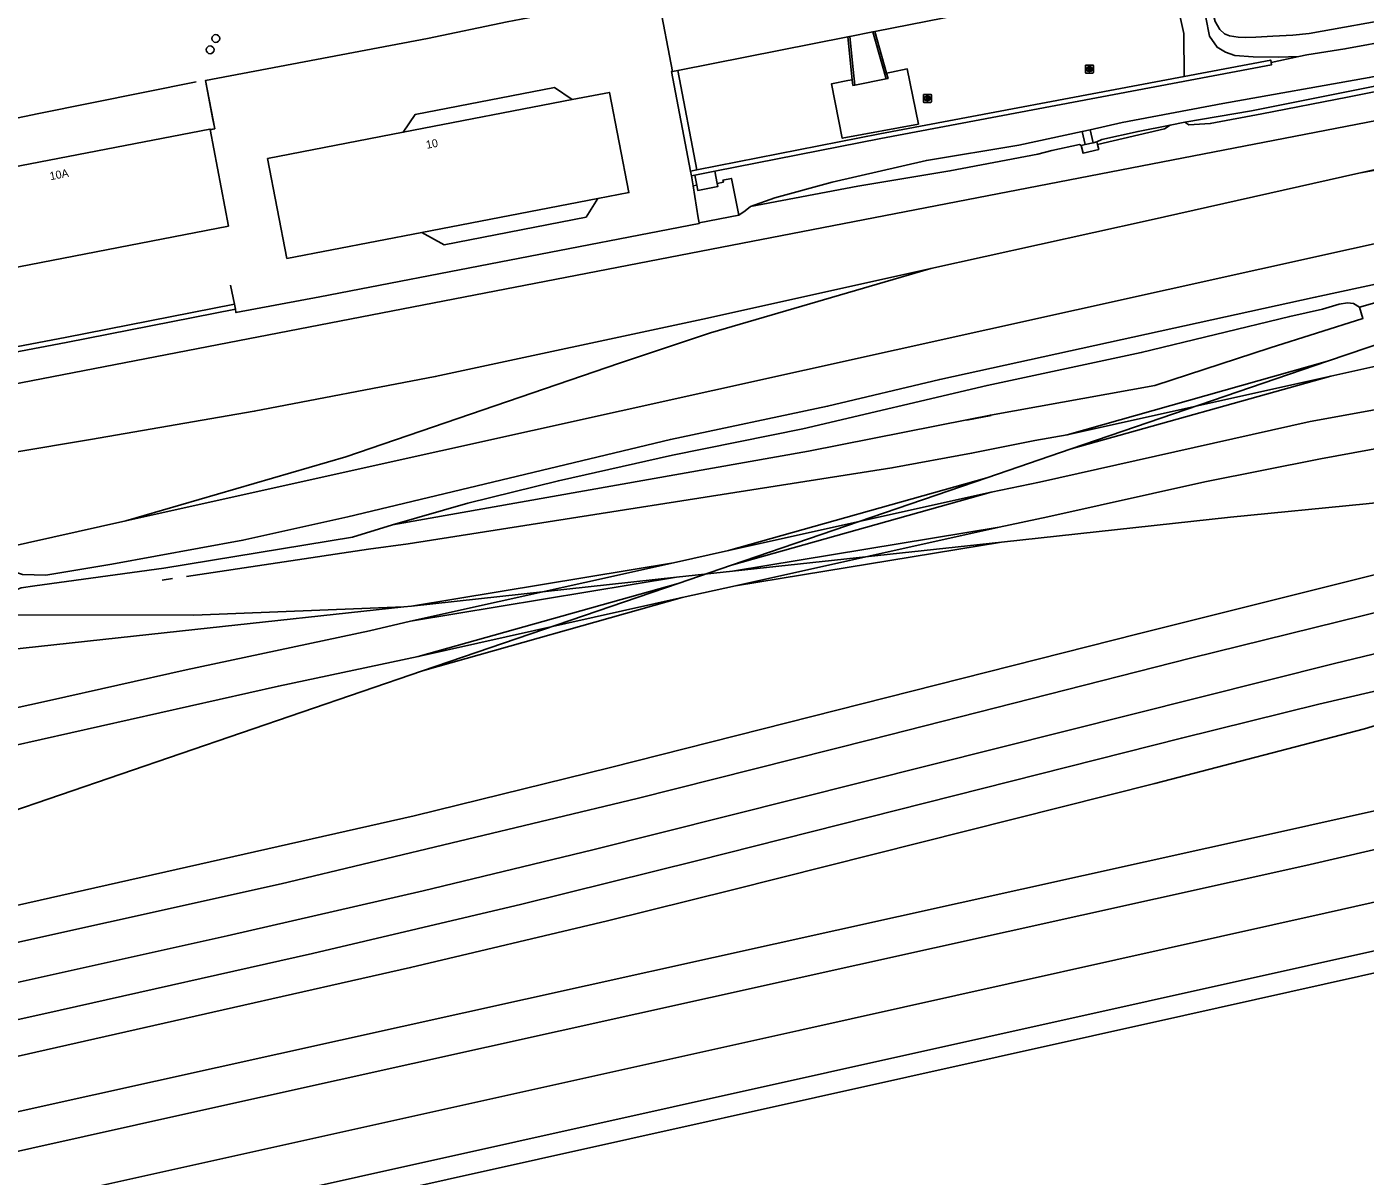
# Model space of a CAD drawing. Extents: x 161477 to 163040, y 383680 to 384868.
# Drawn here: x 161855.5 to 162022.7, y 383800 to 383943.7 of the extents above; entities that cross this region are included whole.
import ezdxf

# ---------------------------------------------------------------- set-up
doc = ezdxf.new("R2010")
doc.units = 0
for name, color, linetype in [('IMGEO_Boom', 7, 'Continuous'), ('IMGEO_Erf', 7, 'Continuous'), ('IMGEO_Grasland_overig', 7, 'Continuous'), ('IMGEO_Groenvoorziening', 7, 'Continuous'), ('IMGEO_Hek', 7, 'Continuous'), ('IMGEO_Loofbos', 7, 'Continuous'), ('IMGEO_Muur', 7, 'Continuous'), ('IMGEO_Pand', 7, 'Continuous'), ('IMGEO_Pand_nummerreeks', 7, 'Continuous'), ('IMGEO_Pand_overbouw', 7, 'Continuous'), ('IMGEO_Parkeervlak_halfverhard', 7, 'Continuous'), ('IMGEO_Rijbaan_lokaal_gesloten', 7, 'Continuous'), ('IMGEO_Rioolput', 7, 'Continuous'), ('IMGEO_Spoor', 7, 'Continuous'), ('IMGEO_Spoorbaan_halfverhard', 7, 'Continuous'), ('IMGEO_Terreindeel_halfverhard', 7, 'Continuous'), ('IMGEO_Terreindeel_onvherhard', 7, 'Continuous'), ('IMGEO_Terreindeel_open', 7, 'Continuous'), ('IMGEO_Voetpad_op_trap', 7, 'Continuous'), ('IMGEO_Waterloop', 7, 'Continuous')]:
    doc.layers.add(name, color=color, linetype=linetype)

msp = doc.modelspace()

# ---------------------------------------------------------------- linework, layer by layer
at = {"layer": 'IMGEO_Boom'}
for centre in [(161879.07, 383942.21), (161878.36, 383940.8)]:
    msp.add_circle(centre, 0.489, dxfattribs=at)
at = {"layer": 'IMGEO_Erf'}
msp.add_lwpolyline([(161936.1, 383938.1), (161934.4, 383947), (161925.12, 383945.87), (161925.09, 383946.14)], dxfattribs=at)
at = {"layer": 'IMGEO_Grasland_overig'}
for points in [[(162042.14, 383941.17), (162039.02, 383940.6), (162023.15, 383937.33), (162004.87, 383934.08), (161992.3, 383931.73), (161988.29, 383930.8)], [(162000.1, 383931.74), (162008.45, 383933.19), (162033.01, 383938.09)], [(161987.31, 383930.57), (161979.37, 383928.9), (161967.83, 383926.98), (161956.08, 383924.25), (161948.92, 383922.3), (161945.86, 383921.22)], [(161998.3, 383931.38), (161994.28, 383930.59), (161989.77, 383929.58), (161989.13, 383929.3)], [(161987.69, 383928.96), (161987.18, 383928.85)], [(161989.13, 383929.3), (161988.66, 383929.19)], [(161989.21, 383928.98), (161989.13, 383929.3)]]:
    msp.add_lwpolyline(points, dxfattribs=at)
at = {"layer": 'IMGEO_Groenvoorziening'}
msp.add_lwpolyline([(161925.09, 383946.14), (161915.47, 383944.28), (161905.53, 383942.23), (161877.77, 383936.95), (161878.93, 383930.93), (161878.36, 383930.82)], dxfattribs=at)
at = {"layer": 'IMGEO_Hek'}
for points in [[(161856.98, 383932.82), (161876.6, 383936.81)], [(161877.77, 383936.95), (161878.66, 383932.31)], [(161839.61, 383929.21), (161856.98, 383932.82)], [(161878.66, 383932.31), (161878.93, 383930.93)], [(161878.93, 383930.93), (161878.31, 383930.81)], [(161880.92, 383911.38), (161881.39, 383909.02), (161881.52, 383908.4), (161881.58, 383907.97), (161892.06, 383909.93), (161939.47, 383919.11), (161939.46, 383919.16), (161939.34, 383919.81), (161938.69, 383923.78), (161938.48, 383925.04), (161938.37, 383925.63)], [(161824.04, 383897.35), (161831.56, 383898.7), (161834.04, 383899.21), (161860.38, 383904.24), (161881.52, 383908.4)], [(161975.92, 383895.12), (161972.88, 383894.51)]]:
    msp.add_lwpolyline(points, dxfattribs=at)
at = {"layer": 'IMGEO_Loofbos'}
for points in [[(162014.37, 383939.95), (162011.76, 383939.87), (162008.65, 383939.9), (162006.37, 383940.1), (162005.22, 383940.5), (162004.15, 383941.12), (162003.21, 383942.49), (162002.73, 383944.84), (162001.35, 383953.25), (161994.44, 384009.28)], [(162010.9, 383939.21), (162014.37, 383939.95)]]:
    msp.add_lwpolyline(points, dxfattribs=at)
at = {"layer": 'IMGEO_Muur'}
for points in [[(161915.47, 383944.28), (161905.53, 383942.23)], [(161877.77, 383936.95), (161905.53, 383942.23)], [(161958.02, 383942.41), (161958.26, 383942.46)], [(161958.58, 383937.05), (161958.02, 383942.41)], [(161958.26, 383942.46), (161958.69, 383938.35), (161958.9, 383936.36)], [(161961.14, 383943.03), (161961.38, 383943.08)], [(161962.8, 383937.16), (161962.26, 383939.08), (161961.14, 383943.03)], [(161961.38, 383943.08), (161962.86, 383937.89)], [(161941.42, 383925.62), (161962.13, 383929.7), (162010.96, 383938.92), (162010.9, 383939.21)], [(162010.9, 383939.21), (162010.85, 383939.51), (162000.03, 383937.46)], [(161936.1, 383938.1), (161935.99, 383938.07), (161938.37, 383925.63)], [(161936.79, 383938.23), (161936.1, 383938.1)], [(161939.17, 383925.79), (161936.79, 383938.23)], [(161939.17, 383925.79), (161962.02, 383930.29), (162000.03, 383937.46)], [(161962.86, 383937.89), (161963.05, 383937.22), (161962.8, 383937.16)], [(161958.9, 383936.36), (161958.65, 383936.34), (161958.58, 383937.05)], [(161938.37, 383925.63), (161939.17, 383925.79)], [(161938.37, 383925.63), (161938.48, 383925.04)], [(161941.42, 383925.62), (161938.9, 383925.12)], [(161938.9, 383925.12), (161938.48, 383925.04)]]:
    msp.add_lwpolyline(points, dxfattribs=at)
at = {"layer": 'IMGEO_Pand'}
for points in [[(161885.53, 383927.22), (161902.48, 383930.5), (161923.58, 383934.58), (161928.25, 383935.48), (161930.67, 383922.96), (161926.81, 383922.22), (161904.82, 383917.98), (161887.95, 383914.72), (161885.53, 383927.22)], [(161878.36, 383930.82), (161880.65, 383918.77), (161847.56, 383912.36), (161842.65, 383911.41), (161840.34, 383923.54), (161840.51, 383923.57)], [(161840.51, 383923.57), (161845.25, 383924.49), (161878.34, 383930.9), (161878.36, 383930.82)], [(162088.04, 383839.79), (162000, 383820.13), (161884.78, 383794.45), (161884.66, 383795.01), (161884.29, 383794.93), (161884.34, 383794.72)]]:
    msp.add_lwpolyline(points, dxfattribs=at)
at = {"layer": 'IMGEO_Pand_overbouw'}
msp.add_lwpolyline([(161966.54, 383987.8), (161967.92, 383976.83), (161965.92, 383976.58), (161968.41, 383956.62), (161969.07, 383951.13), (161955.36, 383949.45), (161955.13, 383951.15), (161955.12, 383951.24), (161924.79, 383947.48), (161924.84, 383947.07), (161924.98, 383947.1), (161925.09, 383946.14), (161925.12, 383945.87), (161934.4, 383947), (161936.1, 383938.1), (161936.79, 383938.23), (161958.02, 383942.41), (161958.26, 383942.46), (161961.14, 383943.03), (161961.38, 383943.08), (161998.35, 383950.36), (161997.81, 383954.73), (161991.65, 383953.96), (161991.53, 383954.6)], dxfattribs=at)
for points in [[(161923.58, 383934.58), (161921.39, 383936.07), (161903.97, 383932.7), (161902.48, 383930.5)], [(161925.32, 383919.88), (161926.81, 383922.22), (161904.82, 383917.98), (161907.59, 383916.44)]]:
    msp.add_lwpolyline(points, close=True, dxfattribs=at)
at = {"layer": 'IMGEO_Parkeervlak_halfverhard'}
for points in [[(161998.35, 383950.36), (161961.38, 383943.08)], [(162000.03, 383937.46), (162000, 383942.85), (161998.35, 383950.36)], [(161958.02, 383942.41), (161936.79, 383938.23)]]:
    msp.add_lwpolyline(points, dxfattribs=at)
at = {"layer": 'IMGEO_Rijbaan_lokaal_gesloten'}
for points in [[(161958.26, 383942.46), (161961.14, 383943.03)], [(161962.86, 383937.89), (161963.47, 383937.99), (161965.45, 383938.41), (161966.84, 383931.52), (161957.33, 383929.74), (161955.99, 383936.55), (161958.01, 383936.95), (161958.58, 383937.05)], [(161958.9, 383936.36), (161962.8, 383937.16)]]:
    msp.add_lwpolyline(points, dxfattribs=at)
at = {"layer": 'IMGEO_Rioolput'}
for p, q in [((161987.71, 383937.96), (161987.71, 383938.81)), ((161987.78, 383938.88), (161988.63, 383938.88)), ((161988.71, 383938.81), (161988.71, 383937.96)), ((161988.63, 383937.88), (161987.78, 383937.88)), ((161988.22, 383938.1), (161988.19, 383938.1)), ((161988.2, 383938.66), (161988.22, 383938.66)), ((161967.46, 383934.29), (161967.46, 383935.15)), ((161967.53, 383935.22), (161968.39, 383935.22)), ((161968.39, 383934.22), (161967.53, 383934.22)), ((161967.95, 383935), (161967.97, 383935)), ((161967.97, 383934.44), (161967.95, 383934.44)), ((161968.46, 383935.15), (161968.46, 383934.29))]:
    msp.add_line(p, q, dxfattribs=at)
for points in [[(161987.71, 383937.96), (161987.71, 383938.81)], [(161987.78, 383938.88), (161988.63, 383938.88)], [(161988.71, 383938.81), (161988.71, 383937.96)], [(161988.63, 383937.88), (161987.78, 383937.88)], [(161988.3, 383938.58), (161988.04, 383938.58), (161988.04, 383938.18)], [(161988.04, 383938.18), (161988.17, 383938.18), (161988.17, 383938.34), (161988.18, 383938.34)], [(161988.22, 383938.5), (161988.17, 383938.5), (161988.17, 383938.42)], [(161988.17, 383938.42), (161988.22, 383938.42)], [(161988.23, 383938.31), (161988.3, 383938.18), (161988.44, 383938.18), (161988.37, 383938.31)], [(161967.46, 383934.29), (161967.46, 383935.15)], [(161967.53, 383935.22), (161968.39, 383935.22)], [(161968.39, 383934.22), (161967.53, 383934.22)], [(161968.05, 383934.92), (161967.8, 383934.92), (161967.8, 383934.52)], [(161967.8, 383934.52), (161967.92, 383934.52), (161967.92, 383934.68), (161967.93, 383934.68)], [(161967.98, 383934.84), (161967.92, 383934.84), (161967.92, 383934.76)], [(161967.92, 383934.76), (161967.97, 383934.76)], [(161967.98, 383934.65), (161968.05, 383934.52), (161968.19, 383934.52), (161968.12, 383934.65)], [(161968.46, 383935.15), (161968.46, 383934.29)]]:
    msp.add_lwpolyline(points, dxfattribs=at)
for centre, radius, start, end in [((161987.78, 383938.81), 0.0765, 91.552, 178.448), ((161987.78, 383938.81), 0.0765, 91.552, 178.448), ((161988.63, 383938.81), 0.0765, 1.552, 88.448), ((161988.63, 383938.81), 0.0765, 1.552, 88.448), ((161987.78, 383937.96), 0.0765, 181.552, 268.448), ((161987.78, 383937.96), 0.0765, 181.552, 268.448), ((161988.18, 383938.29), 0.0533, 26.0293, 88.6989), ((161988.23, 383938.4), 0.0964, 77.0061, 93.1865), ((161988.2, 383938.61), 0.19, 274.7715, 282.9687), ((161988.24, 383938.46), 0.0378, 276.6634, 79.6772), ((161988.3, 383938.47), 0.109, 350.3612, 89.416), ((161988.29, 383938.47), 0.112, 277.5842, 350.9817), ((161988.28, 383938.25), 0.108, 29.5134, 73.7905), ((161988.63, 383937.96), 0.0765, 271.552, 358.448), ((161988.63, 383937.96), 0.0765, 271.552, 358.448), ((161967.54, 383935.14), 0.0765, 91.552, 178.448), ((161967.54, 383935.14), 0.0765, 91.552, 178.448), ((161967.54, 383934.3), 0.0765, 181.552, 268.448), ((161967.54, 383934.3), 0.0765, 181.552, 268.448), ((161967.93, 383934.63), 0.0533, 26.0293, 88.6989), ((161967.96, 383934.95), 0.19, 274.7715, 282.9687), ((161967.98, 383934.74), 0.0964, 77.0061, 93.1865), ((161968, 383934.8), 0.0378, 276.6634, 79.6772), ((161968.05, 383934.81), 0.109, 350.3612, 89.416), ((161968.05, 383934.81), 0.112, 277.5842, 350.9817), ((161968.03, 383934.59), 0.108, 29.5134, 73.7905), ((161968.38, 383935.14), 0.0765, 1.552, 88.448), ((161968.38, 383935.14), 0.0765, 1.552, 88.448), ((161968.38, 383934.3), 0.0765, 271.552, 358.448), ((161968.38, 383934.3), 0.0765, 271.552, 358.448)]:
    msp.add_arc(centre, radius, start, end, dxfattribs=at)
for centre, major_axis, ratio, start_param, end_param in [((161988.19, 383938.38), (-0.387, 0.002), 0.722429, 4.712389, 7.853982), ((161988.22, 383938.38), (-0.39, 0.002), 0.717154, 1.570796, 4.712389), ((161967.95, 383934.72), (-0.387, 0.002), 0.722429, 4.712389, 7.853982), ((161967.97, 383934.72), (-0.39, 0.002), 0.717154, 1.570796, 4.712389)]:
    msp.add_ellipse(centre, major_axis=major_axis, ratio=ratio, start_param=start_param, end_param=end_param, dxfattribs=at)
at = {"layer": 'IMGEO_Spoor'}
for points in [[(161983.02, 383882.43), (162002.6, 383886.8), (162017.08, 383889.7), (162027.28, 383891.57), (162036.3, 383892.96), (162053.1, 383895.33), (162060.81, 383896.33), (162085.72, 383899.26), (162099.11, 383900.95), (162110.01, 383902.48), (162119.36, 383903.88), (162127.92, 383905.34), (162136.6, 383906.89), (162146.67, 383908.84), (162166.54, 383913.05), (162267.83, 383935.63), (162298.18, 383942.49), (162368.54, 383958.02), (162456.6, 383977.62)], [(161981.95, 383886.79), (162015.79, 383894.36), (162029.29, 383896.79), (162043.99, 383899.13), (162058.27, 383900.92), (162089.66, 383904.4), (162105.43, 383905.98), (162116.55, 383907.59), (162125.44, 383909.1), (162136.16, 383911.23), (162167.56, 383918.35), (162190.79, 383923.42), (162250.53, 383936.75), (162372.17, 383963.7)], [(162082.22, 383940.62), (162067.16, 383939.08), (162060.65, 383938.31), (162050.14, 383936.84), (162039.55, 383934.98), (161761.26, 383881.1), (161737.23, 383876.55), (161717.53, 383872.76)], [(162111.79, 383936.09), (161895.74, 383888.14)], [(162068.85, 383935.78), (162021.85, 383925.39)], [(162069.13, 383934.01), (162021.85, 383925.39)], [(161750.33, 383784.82), (161856.15, 383808.49), (162010.58, 383842.76), (162025.33, 383846.04), (162038.44, 383849.14), (162081.87, 383858.91), (162203.93, 383886.62), (162328.82, 383914.89), (162363.46, 383922.8), (162370.5, 383924.21), (162377.8, 383925.46), (162384.63, 383926.4), (162393.03, 383927.13), (162402.21, 383927.44), (162408.98, 383927.48)], [(161752.19, 383780.4), (161875.71, 383807.94), (162015.25, 383838.88), (162036.64, 383843.84), (162104.75, 383859.25), (162247.6, 383891.59), (162328.95, 383910.05), (162367.14, 383918.71), (162379.68, 383921.18), (162389.53, 383922.69), (162398.92, 383923.74), (162409, 383924.59)], [(162021.85, 383925.39), (161995.56, 383919.47), (161968.4, 383913.47)], [(161754.68, 383774.37), (161849.16, 383795.44), (161951.91, 383818.25), (162017.67, 383832.92), (162036.57, 383837.16), (162110.8, 383854.02), (162201.33, 383874.48), (162299.92, 383896.88), (162339.11, 383905.77), (162371.6, 383913.13), (162387.02, 383916.6), (162393.33, 383917.81), (162399.33, 383918.84), (162404.24, 383919.61), (162409.95, 383920.31), (162415.59, 383920.88), (162421.26, 383921.34), (162428.5, 383921.74), (162433.31, 383921.88), (162439.75, 383921.91), (162444.26, 383921.83)], [(161968.4, 383913.47), (161940.49, 383907.28)], [(161968.4, 383913.47), (161940.86, 383905.43)], [(161940.49, 383907.28), (161906.48, 383899.97), (161883.87, 383895.64), (161863.41, 383892.09), (161749.22, 383872.99)], [(161940.86, 383905.43), (161929.51, 383901.63), (161895.3, 383889.92)], [(162030.37, 383906.11), (162017.93, 383901.87)], [(162017.93, 383901.87), (161985.42, 383892.7)], [(162017.93, 383901.87), (161985.93, 383890.92)], [(162026.21, 383901.77), (162018.35, 383900.01)], [(162018.35, 383900.01), (161985.42, 383892.7)], [(162018.35, 383900.01), (161985.93, 383890.92)], [(161756.53, 383768.76), (161838.28, 383786.93), (161975.14, 383817.36), (162056.37, 383835.44), (162106.4, 383846.65), (162114.63, 383848.32), (162125.79, 383850.6), (162135.24, 383852.23), (162143.31, 383853.7), (162150.4, 383855), (162159.12, 383856.88), (162165.31, 383858.26), (162254.85, 383878.09), (162292.54, 383886.49), (162314.34, 383891.26), (162320.37, 383892.65), (162328.36, 383894.6), (162337.4, 383896.88)], [(162120.88, 383892.68), (162062.31, 383879.66), (162037.81, 383873.92), (162000.83, 383864.78), (161960.94, 383854.6), (161931.69, 383847.23), (161887.22, 383836.56), (161822.48, 383822.2), (161794.19, 383815.83), (161768.23, 383810.18), (161751.35, 383806.22), (161742.18, 383804.14)], [(161985.42, 383892.7), (161981.38, 383891.97), (161973.49, 383890.38), (161963.54, 383888.55), (161903.11, 383879.05), (161898.15, 383878.4), (161875.4, 383874.99)], [(161985.93, 383890.92), (161975.37, 383887.31)], [(161895.3, 383889.92), (161867.83, 383881.94)], [(162080.1, 383890.11), (162022.76, 383884.07), (162005.83, 383882.41), (161977.21, 383879.26)], [(162124.71, 383888.45), (162110.92, 383885.28), (162073.48, 383876.95), (162044.87, 383870.41), (162018.83, 383864.1), (161926.17, 383840.83), (161904.99, 383835.71), (161880.47, 383830.07), (161744.04, 383799.74)], [(162080.4, 383888.27), (162044.96, 383880.31), (162029.1, 383876.52), (161994.28, 383867.84), (161928.36, 383851.12), (161903.85, 383845.06), (161837.13, 383830.06), (161814.39, 383825.1), (161790.23, 383819.66), (161771.31, 383815.49)], [(161895.74, 383888.14), (161867.83, 383881.94)], [(161975.37, 383887.31), (161943.11, 383878.24)], [(161975.37, 383887.31), (161943.5, 383876.41)], [(161975.91, 383885.54), (161943.11, 383878.24)], [(161975.91, 383885.54), (161943.5, 383876.41)], [(161981.95, 383886.79), (161975.91, 383885.54)], [(161983.02, 383882.43), (161976.94, 383881.14)], [(161867.83, 383881.94), (161824.99, 383872.35)], [(161976.94, 383881.14), (161943.63, 383875.63)], [(161976.94, 383881.14), (161943.99, 383873.82)], [(161977.21, 383879.26), (161943.63, 383875.63)], [(161977.21, 383879.26), (161943.99, 383873.82)], [(161943.11, 383878.24), (161936.25, 383876.68)], [(161936.25, 383876.68), (161903.4, 383869.39)], [(161936.25, 383876.68), (161903.53, 383871.27)], [(161943.63, 383875.63), (161936.62, 383874.88)], [(161943.5, 383876.41), (161936.81, 383874.11)], [(161872.38, 383874.53), (161873.67, 383874.73)], [(161936.62, 383874.88), (161903.4, 383869.39)], [(161936.62, 383874.88), (161903.53, 383871.27)], [(161936.81, 383874.11), (161904.37, 383865)], [(161936.81, 383874.11), (161904.91, 383863.21)], [(161943.99, 383873.82), (161937.31, 383872.34)], [(161937.31, 383872.34), (161904.37, 383865)], [(161937.31, 383872.34), (161904.91, 383863.21)], [(161902.54, 383871.18), (161876.34, 383870.15)], [(161902.54, 383871.18), (161876.44, 383868.34)], [(161903.53, 383871.27), (161902.54, 383871.18)], [(161903.4, 383869.39), (161898.27, 383868.21), (161875.37, 383863.33), (161858.28, 383859.48), (161835.18, 383854.42), (161757.45, 383836.94), (161730.85, 383831.03)], [(161876.34, 383870.15), (161825.18, 383870.21)], [(161876.44, 383868.34), (161792.91, 383859.3)], [(162046.51, 383865.9), (162016.88, 383859.02), (161999.7, 383854.79), (161939.27, 383839.49), (161917.3, 383834.06), (161891.14, 383827.89), (161859.61, 383820.78), (161745.83, 383795.49)], [(161904.37, 383865), (161886.89, 383861.28), (161827.55, 383847.97), (161732.61, 383826.84)], [(162046.94, 383863.93), (162029.39, 383858.02), (162022.57, 383855.93), (161996.39, 383849.13), (161943.61, 383835.84), (161927.99, 383831.97), (161903.41, 383826.11), (161837, 383811.15), (161747.6, 383791.29)], [(161904.91, 383863.21), (161784.26, 383821.87), (161770.68, 383817.3)]]:
    msp.add_lwpolyline(points, dxfattribs=at)
at = {"layer": 'IMGEO_Spoorbaan_halfverhard'}
for points in [[(162000.1, 383931.74), (162000.62, 383931.44), (162003.29, 383931.57), (162009.73, 383932.78), (162020.44, 383934.88), (162031.92, 383937.16), (162033.01, 383938.09)], [(161989.21, 383928.98), (161997.59, 383930.91), (161998.3, 383931.38)], [(161998.3, 383931.38), (162000.1, 383931.74)], [(161945.86, 383921.22), (161959.28, 383923.76), (161970.77, 383925.67), (161981.75, 383927.74), (161983.51, 383928.2), (161986.97, 383928.96), (161987.18, 383928.85)], [(161987.18, 383928.85), (161987.41, 383927.87), (161989.36, 383928.33), (161989.21, 383928.98)], [(162073.21, 383922.46), (162072.53, 383924.91), (162063.15, 383922.83), (162033.18, 383913.65), (162025.1, 383911.78), (162016.42, 383909.88), (161969.5, 383899.62), (161955.5, 383896.25), (161935.87, 383892.12), (161895.58, 383882.44), (161882.46, 383879.52), (161866.09, 383876.54), (161857.82, 383875.17), (161854.93, 383875.23), (161854.41, 383875.41), (161853.62, 383875.68), (161852.46, 383876.8)], [(162021.92, 383908.64), (162035.31, 383912.41), (162057.55, 383919.14), (162067.13, 383922.13), (162070.18, 383922.99), (162071.54, 383921.92)], [(161945.86, 383921.22), (161945.18, 383920.67), (161944.4, 383920.14)], [(161881.52, 383908.4), (161881.58, 383907.97), (161892.06, 383909.93), (161939.47, 383919.11), (161939.46, 383919.16)], [(161939.46, 383919.16), (161944.4, 383920.14)], [(161785.51, 383889.91), (161792.64, 383891.29), (161800.01, 383892.71), (161812.23, 383895.08), (161824.04, 383897.35), (161831.56, 383898.7), (161834.04, 383899.21), (161860.38, 383904.24), (161881.52, 383908.4)], [(161901.16, 383881.46), (161953.13, 383890.66), (161973.08, 383894.6), (161975.84, 383895.15), (161996.39, 383898.83), (162010.79, 383903.57), (162022.37, 383907.22), (162021.92, 383908.64)], [(161851.46, 383871.84), (161852.6, 383873.07), (161854.35, 383873.42), (161854.77, 383873.55), (161856.45, 383873.8), (161872.57, 383876.01), (161896.14, 383879.9), (161901.16, 383881.46)]]:
    msp.add_lwpolyline(points, dxfattribs=at)
at = {"layer": 'IMGEO_Terreindeel_halfverhard'}
msp.add_lwpolyline([(161901.16, 383881.46), (161910.54, 383884.16), (161921.86, 383886.94), (161936.13, 383890.16), (161952.4, 383893.45), (161975.41, 383898.85), (161994.68, 383902.97), (162013.22, 383907.48), (162017.32, 383908.39), (162019.42, 383909.03), (162020.45, 383909.19), (162021.2, 383909.1), (162021.92, 383908.64)], dxfattribs=at)
at = {"layer": 'IMGEO_Terreindeel_onvherhard'}
for points in [[(162014.37, 383939.95), (162015.38, 383940.16), (162020.11, 383940.9), (162032.85, 383943.24), (162042, 383944.92), (162043.3, 383945.44), (162044.34, 383946.02), (162044.79, 383947.17), (162044.8, 383947.25)], [(161938.48, 383925.04), (161938.69, 383923.78)]]:
    msp.add_lwpolyline(points, dxfattribs=at)
at = {"layer": 'IMGEO_Terreindeel_open'}
for points in [[(161941.72, 383924.1), (161941.42, 383925.62)], [(161938.69, 383923.78), (161939.15, 383923.87)], [(161938.69, 383923.78), (161939.34, 383919.81), (161939.46, 383919.16)], [(161939.15, 383923.87), (161938.9, 383925.12)], [(161941.72, 383924.1), (161941.79, 383923.73), (161939.27, 383923.23), (161939.15, 383923.87)], [(161944.4, 383920.14), (161943.49, 383924.73), (161942.42, 383924.52), (161942.48, 383924.25), (161941.72, 383924.1)], [(161822.03, 383907.56), (161822.96, 383907.74), (161823.62, 383904.23), (161824.71, 383898.53), (161827.07, 383898.98), (161827.15, 383898.54), (161831.44, 383899.32), (161833.92, 383899.83), (161860.26, 383904.85), (161881.39, 383909.02), (161881.52, 383908.4)]]:
    msp.add_lwpolyline(points, dxfattribs=at)
at = {"layer": 'IMGEO_Voetpad_op_trap'}
for points in [[(161988.29, 383930.8), (161987.31, 383930.57)], [(161987.31, 383930.57), (161987.69, 383928.96)], [(161988.66, 383929.19), (161988.29, 383930.8)], [(161987.69, 383928.96), (161988.66, 383929.19)]]:
    msp.add_lwpolyline(points, dxfattribs=at)
at = {"layer": 'IMGEO_Waterloop'}
msp.add_lwpolyline([(162042.8, 383947.53), (162027.26, 383944.91), (162015.67, 383942.85), (162013.62, 383942.64), (162011.1, 383942.5), (162008.99, 383942.39), (162007.72, 383942.33), (162006.8, 383942.38), (162005.69, 383942.55), (162005.09, 383942.79), (162004.51, 383943.35), (162003.92, 383944.32), (162003.31, 383946.55), (161996.63, 384000.2), (161995.62, 384009.96)], dxfattribs=at)

# ---------------------------------------------------------------- texts
at = {"layer": 'IMGEO_Pand_nummerreeks'}
for s, rotation, p in [('10', 10.7659, (161905.43, 383928.42)), ('10A', 10.7601, (161858.42, 383924.5))]:
    msp.add_text(s, height=1, rotation=rotation, dxfattribs=at).set_placement(p)

doc.saveas('drawing.dxf')
